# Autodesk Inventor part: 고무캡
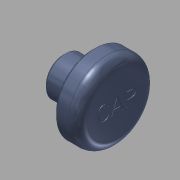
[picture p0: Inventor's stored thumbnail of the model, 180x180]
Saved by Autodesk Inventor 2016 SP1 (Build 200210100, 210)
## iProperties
Created: 2017-06
Part Number: 고무캡
Material: 고무
Document SubType Name: Modeling
Designer: mduedu
Density: 1 g/cm^3
Appearance: 고무 - 파란색 - 버전 1.1
Author: mduedu
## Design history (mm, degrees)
sketch "스케치1"
  geometry: L1 (0, 0)-(11, 0); L2 (11, 0)-(11, 8); L3 (11, 8)-(6.5, 8); L4 (0, 4)-(0, 0); L5 (0, 4)-(6, 4); L6 (6, 4)-(6, 7.5); L7 (6, 7.5)-(6.5, 7.5); L8 (6.5, 7.5)-(6.5, 8)
  constraints: 16 end point, 2 horizontal, 2 parallel, 2 perpendicular, 2 point on line, 1 vertical
  dimensions: "d0" = 16 diameter of L3 L1; "d2" = 8 diameter of L5 L1; "d6" = 5 distance between parallel lines of L2 L6; "d7" = 0.5 distance between parallel lines of L8 L6; "d8" = 15 diameter of L7 L1; "d9" = 6 distance between parallel lines of L6 L4
revolve "회전1" sketch "스케치1" stored, may be unused: angle "d10" = 90 deg
hole "구멍1" diameter "d22" = 5; stored, may be unused: countersink angle "d26" = 90 deg, drill point angle "d28" = 0 deg; dims "d23" = 6, "d24" = 4, "d25" = 2, "d27" = 6, "d30" = 10, "d31" = 10
chamfer "모따기1" distance "d13" = 0.5; stored, may be unused: second distance "d14" = 2, angle "d15" = 45 deg
fillet "모깎기3" dims "d29" = 1
fillet "모깎기1" dims "d16" = 0.1
fillet "모깎기2" dims "d17" = 2
sketch "스케치3"
  geometry: 2 further points
  constraints: 1 coincident, 1 other
feature "엠보싱1" sketch "스케치3" dims "d18" = 0.2, "d19" = 0
node "솔리드1"
